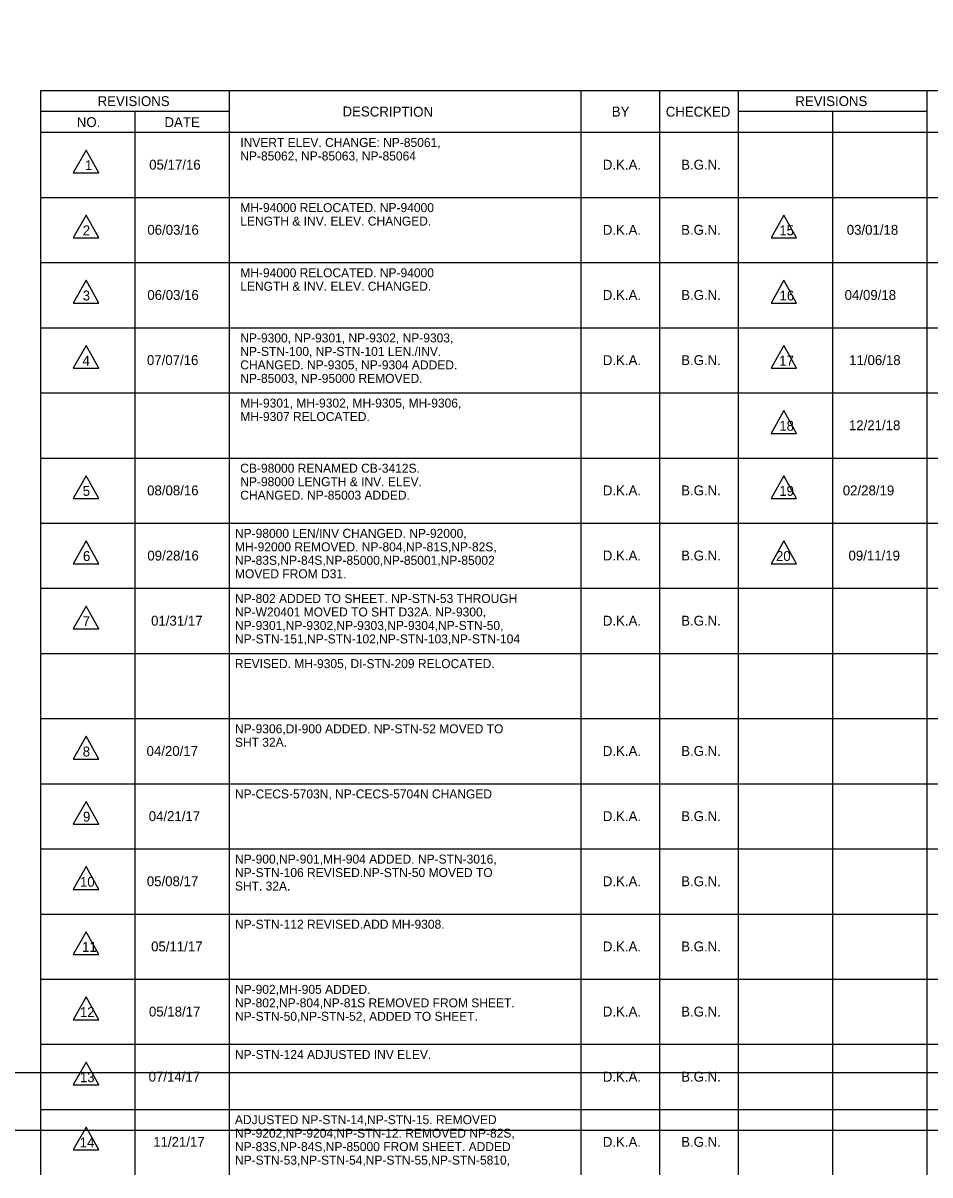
# Model space of a CAD drawing. Extents: x 260980 to 262786, y 322332 to 323393.
# Drawn here: x 261936 to 262340, y 322332 to 322845 of the extents above; entities that cross this region are included whole.
import ezdxf

# ---------------------------------------------------------------- set-up
doc = ezdxf.new("R2010")
doc.units = 0
for name, color, linetype in [('Level 23', 7, 'Continuous'), ('Level 5', 7, 'Continuous'), ('RD_SHT_TX', 7, 'Continuous')]:
    doc.layers.add(name, color=color, linetype=linetype)

msp = doc.modelspace()

# ---------------------------------------------------------------- linework, layer by layer
at = {"layer": 'Level 23'}
msp.add_lwpolyline([(261111.06, 323336.45), (262761.54, 323336.45), (262761.54, 322351.79), (261111.06, 322351.79)], close=True, dxfattribs=at)
msp.add_lwpolyline([(261111.06, 323336.45), (262761.54, 323336.45), (262761.54, 322351.79), (261111.06, 322351.79)], close=True, dxfattribs=at)
at = {"layer": 'Level 5'}
msp.add_lwpolyline([(261111.06, 323310.45), (262762.33, 323310.45), (262762.33, 322377.34), (261111.06, 322377.34)], close=True, dxfattribs=at)
at = {"layer": 'RD_SHT_TX'}
for p, q in [((261944.02, 322814.63), (262254.62, 322814.63)), ((261944.02, 322331.93), (261944.02, 322814.63)), ((262028.02, 322331.93), (262028.02, 322814.63)), ((262184.62, 322331.93), (262184.62, 322814.63)), ((262219.62, 322331.93), (262219.62, 322814.63)), ((262254.62, 322331.93), (262254.62, 322814.63)), ((262254.62, 322814.63), (262565.22, 322814.63)), ((262338.62, 322331.93), (262338.62, 322814.63)), ((262028.02, 322805.28), (261944.02, 322805.28)), ((261986.02, 322331.93), (261986.02, 322805.28)), ((262338.62, 322805.28), (262254.62, 322805.28)), ((262296.62, 322331.93), (262296.62, 322805.28)), ((262565.22, 322795.93), (261944.02, 322795.93)), ((261964.18, 322788.19), (261958.49, 322778.05)), ((261969.88, 322778.05), (261964.18, 322788.19)), ((261958.49, 322778.05), (261969.88, 322778.05)), ((262565.22, 322766.93), (261944.02, 322766.93)), ((261964.18, 322759.19), (261958.49, 322749.05)), ((261969.88, 322749.05), (261964.18, 322759.19)), ((262274.78, 322759.19), (262269.09, 322749.05)), ((262280.48, 322749.05), (262274.78, 322759.19)), ((261958.49, 322749.05), (261969.88, 322749.05)), ((262269.09, 322749.05), (262280.48, 322749.05)), ((262565.22, 322737.93), (261944.02, 322737.93)), ((261964.18, 322730.19), (261958.49, 322720.05)), ((261969.88, 322720.05), (261964.18, 322730.19)), ((262274.78, 322730.19), (262269.09, 322720.05)), ((262280.48, 322720.05), (262274.78, 322730.19)), ((261958.49, 322720.05), (261969.88, 322720.05)), ((262269.09, 322720.05), (262280.48, 322720.05)), ((262565.22, 322708.93), (261944.02, 322708.93)), ((261964.18, 322701.19), (261958.49, 322691.05)), ((261969.88, 322691.05), (261964.18, 322701.19)), ((262274.78, 322701.19), (262269.09, 322691.05)), ((262280.48, 322691.05), (262274.78, 322701.19)), ((261958.49, 322691.05), (261969.88, 322691.05)), ((262269.09, 322691.05), (262280.48, 322691.05)), ((262565.22, 322679.93), (261944.02, 322679.93)), ((262274.78, 322672.19), (262269.09, 322662.05)), ((262280.48, 322662.05), (262274.78, 322672.19)), ((262269.09, 322662.05), (262280.48, 322662.05)), ((262565.22, 322650.93), (261944.02, 322650.93)), ((261964.19, 322643.19), (261958.49, 322633.05)), ((261969.88, 322633.05), (261964.19, 322643.19)), ((262274.78, 322643.19), (262269.09, 322633.05)), ((262280.48, 322633.05), (262274.78, 322643.19)), ((261958.49, 322633.05), (261969.88, 322633.05)), ((262269.09, 322633.05), (262280.48, 322633.05)), ((262565.22, 322621.93), (261944.02, 322621.93)), ((261964.19, 322614.19), (261958.49, 322604.05)), ((261969.88, 322604.05), (261964.19, 322614.19)), ((262274.78, 322614.19), (262269.09, 322604.05)), ((262280.48, 322604.05), (262274.78, 322614.19)), ((261958.49, 322604.05), (261969.88, 322604.05)), ((262269.09, 322604.05), (262280.48, 322604.05)), ((262565.22, 322592.93), (261944.02, 322592.93)), ((261964.19, 322585.19), (261958.49, 322575.05)), ((261969.88, 322575.05), (261964.19, 322585.19)), ((261958.49, 322575.05), (261969.88, 322575.05)), ((262565.22, 322563.93), (261944.02, 322563.93)), ((262565.22, 322534.93), (261944.02, 322534.93)), ((261964.19, 322527.19), (261958.49, 322517.05)), ((261969.88, 322517.05), (261964.19, 322527.19)), ((261958.49, 322517.05), (261969.88, 322517.05)), ((262565.22, 322505.93), (261944.02, 322505.93)), ((261964.19, 322498.19), (261958.49, 322488.05)), ((261969.88, 322488.05), (261964.19, 322498.19)), ((261958.49, 322488.05), (261969.88, 322488.05)), ((262565.22, 322476.93), (261944.02, 322476.93)), ((261964.19, 322469.19), (261958.49, 322459.05)), ((261969.88, 322459.05), (261964.19, 322469.19)), ((261958.49, 322459.05), (261969.88, 322459.05)), ((262565.22, 322447.93), (261944.02, 322447.93)), ((261964.19, 322440.19), (261958.49, 322430.05)), ((261969.88, 322430.05), (261964.19, 322440.19)), ((261958.49, 322430.05), (261969.88, 322430.05)), ((262565.22, 322418.93), (261944.02, 322418.93)), ((261964.19, 322411.19), (261958.49, 322401.05)), ((261969.88, 322401.05), (261964.19, 322411.19)), ((261958.49, 322401.05), (261969.88, 322401.05)), ((262565.22, 322389.93), (261944.02, 322389.93)), ((261964.19, 322382.19), (261958.49, 322372.05)), ((261969.88, 322372.05), (261964.19, 322382.19)), ((261958.49, 322372.05), (261969.88, 322372.05)), ((262565.22, 322360.93), (261944.02, 322360.93)), ((261964.19, 322353.19), (261958.49, 322343.05)), ((261969.88, 322343.05), (261964.19, 322353.19)), ((261958.49, 322343.05), (261969.88, 322343.05))]:
    msp.add_line(p, q, dxfattribs=at)

# ---------------------------------------------------------------- texts
for s, p in [('REVISIONS', (261969.31, 322807.75)), ('REVISIONS', (262279.91, 322807.75)), ('CHECKED', (262222.22, 322803.05)), ('NO.', (261960.04, 322798.4)), ('1', (261963.65, 322779.23)), ('2', (261962.68, 322750.23)), ('15', (262272.73, 322750.23)), ('3', (261962.68, 322721.23)), ('16', (262272.84, 322721.23)), ('4', (261962.57, 322692.23)), ('17', (262272.7, 322692.23)), ('18', (262272.73, 322663.23)), ('5', (261962.68, 322634.23)), ('19', (262272.73, 322634.23)), ('6', (261962.79, 322605.23)), ('20', (262271.28, 322605.23)), ('7', (261962.64, 322576.23)), ('8', (261962.68, 322518.23)), ('9', (261962.79, 322489.23)), ('10', (261961.44, 322460.23)), ('11', (261962.38, 322431.23)), ('12', (261961.4, 322402.23)), ('13', (261961.4, 322373.23)), ('14', (261961.3, 322344.23))]:
    msp.add_text(s, height=4.4, dxfattribs=at).set_placement(p)
for s, height, rotation, p in [('DESCRIPTION', 4.4083, 359.7246, (262078.32, 322803.17)), ('BY', 4.408, 359.7246, (262198.18, 322803.09)), ('DATE', 4.408, 359.7246, (261999.05, 322798.43)), ('INVERT ELEV. CHANGE: NP-85061,', 4, 360, (262032.81, 322789.54)), ('05/17/16', 4.4, 360, (261992.27, 322779.46)), ('NP-85062, NP-85063, NP-85064', 4, 360, (262032.81, 322783.54)), ('D.K.A.', 4.4, 360, (262194.21, 322779.46)), ('B.G.N.', 4.4, 360, (262229.09, 322779.46)), ('MH-94000 RELOCATED. NP-94000 ', 4, 360, (262032.81, 322760.54)), ('LENGTH & INV. ELEV. CHANGED.', 4, 360, (262032.81, 322754.54)), ('06/03/16', 4.4, 360, (261991.45, 322750.46)), ('D.K.A.', 4.4, 360, (262194.21, 322750.46)), ('B.G.N.', 4.4, 360, (262229.08, 322750.46)), ('03/01/18', 4.4, 360, (262302.79, 322750.46)), ('MH-94000 RELOCATED. NP-94000 ', 4, 360, (262032.81, 322731.54)), ('LENGTH & INV. ELEV. CHANGED.', 4, 360, (262032.81, 322725.54)), ('06/03/16', 4.4, 360, (261991.45, 322721.46)), ('D.K.A.', 4.4, 360, (262194.21, 322721.46)), ('B.G.N.', 4.4, 360, (262229.09, 322721.46)), ('04/09/18', 4.4, 360, (262301.84, 322721.46)), ('NP-9300, NP-9301, NP-9302, NP-9303,', 4, 360, (262032.81, 322702.54)), ('07/07/16', 4.4, 360, (261991.27, 322692.46)), ('NP-STN-100, NP-STN-101 LEN./INV.', 4, 360, (262032.81, 322696.54)), ('D.K.A.', 4.4, 360, (262194.21, 322692.46)), ('B.G.N.', 4.4, 360, (262229.09, 322692.46)), ('11/06/18', 4.4, 360, (262303.86, 322692.46)), ('CHANGED. NP-9305, NP-9304 ADDED.', 4, 360, (262032.81, 322690.54)), ('NP-85003, NP-95000 REMOVED.', 4, 360, (262032.81, 322684.54)), ('MH-9301, MH-9302, MH-9305, MH-9306,', 4, 360, (262032.81, 322673.54)), ('MH-9307 RELOCATED. ', 4, 360, (262032.81, 322667.54)), ('12/21/18', 4.4, 360, (262303.75, 322663.46)), ('CB-98000 RENAMED CB-3412S.', 4, 360, (262032.81, 322644.54)), ('NP-98000 LENGTH & INV. ELEV.', 4, 360, (262032.81, 322638.54)), ('08/08/16', 4.4, 360, (261991.35, 322634.46)), ('CHANGED. NP-85003 ADDED.', 4, 360, (262032.81, 322632.54)), ('D.K.A.', 4.4, 360, (262194.21, 322634.46)), ('B.G.N.', 4.4, 360, (262229.09, 322634.46)), ('02/28/19', 4.4, 360, (262301.02, 322634.46)), ('NP-98000 LEN/INV CHANGED. NP-92000, ', 4, 360, (262030.43, 322615.54)), ('09/28/16', 4.4, 360, (261991.45, 322605.46)), ('MH-92000 REMOVED. NP-804,NP-81S,NP-82S,', 4, 360, (262030.43, 322609.54)), ('D.K.A.', 4.4, 360, (262194.21, 322605.46)), ('B.G.N.', 4.4, 360, (262229.09, 322605.46)), ('09/11/19', 4.4, 360, (262303.57, 322605.46)), ('NP-83S,NP-84S,NP-85000,NP-85001,NP-85002', 4, 360, (262030.43, 322603.54)), ('MOVED FROM D31.', 4, 360, (262030.43, 322597.54)), ('NP-802 ADDED TO SHEET. NP-STN-53 THROUGH ', 4, 360, (262030.43, 322586.54)), ('NP-W20401 MOVED TO SHT D32A. NP-9300,', 4, 360, (262030.43, 322580.54)), ('01/31/17', 4.4, 360, (261993.12, 322576.46)), ('D.K.A.', 4.4, 360, (262194.21, 322576.46)), ('B.G.N.', 4.4, 360, (262229.09, 322576.46)), ('NP-9301,NP-9302,NP-9303,NP-9304,NP-STN-50,', 4, 360, (262030.43, 322574.54)), ('NP-STN-151,NP-STN-102,NP-STN-103,NP-STN-104', 4, 360, (262030.43, 322568.54)), ('REVISED. MH-9305, DI-STN-209 RELOCATED.', 4, 360, (262030.43, 322557.54)), ('NP-9306,DI-900 ADDED. NP-STN-52 MOVED TO', 4, 360, (262030.43, 322528.54)), ('04/20/17', 4.4, 360, (261991.1, 322518.46)), ('SHT 32A.', 4, 360, (262030.43, 322522.54)), ('D.K.A.', 4.4, 360, (262194.21, 322518.46)), ('B.G.N.', 4.4, 360, (262229.09, 322518.46)), ('NP-CECS-5703N, NP-CECS-5704N CHANGED', 4, 360, (262030.43, 322499.54)), ('04/21/17', 4.4, 360, (261992.05, 322489.46)), ('D.K.A.', 4.4, 360, (262194.21, 322489.46)), ('B.G.N.', 4.4, 360, (262229.09, 322489.46)), ('NP-900,NP-901,MH-904 ADDED. NP-STN-3016,', 4, 360, (262030.43, 322470.54)), ('NP-STN-106 REVISED.NP-STN-50 MOVED TO', 4, 360, (262030.43, 322464.54)), ('05/08/17', 4.4, 360, (261991.2, 322460.46)), ('SHT. 32A.', 4, 360, (262030.43, 322458.54)), ('D.K.A.', 4.4, 360, (262194.21, 322460.46)), ('B.G.N.', 4.4, 360, (262229.09, 322460.46)), ('NP-STN-112 REVISED.ADD MH-9308.', 4, 360, (262030.43, 322441.54)), ('05/11/17', 4.4, 360, (261993.12, 322431.46)), ('D.K.A.', 4.4, 360, (262194.21, 322431.46)), ('B.G.N.', 4.4, 360, (262229.09, 322431.46)), ('NP-902,MH-905 ADDED.', 4, 360, (262030.43, 322412.54)), ('NP-802,NP-804,NP-81S REMOVED FROM SHEET.', 4, 360, (262030.43, 322406.54)), ('05/18/17', 4.4, 360, (261992.16, 322402.46)), ('NP-STN-50,NP-STN-52, ADDED TO SHEET.', 4, 360, (262030.43, 322400.54)), ('D.K.A.', 4.4, 360, (262194.21, 322402.46)), ('B.G.N.', 4.4, 360, (262229.09, 322402.46)), ('NP-STN-124 ADJUSTED INV ELEV.', 4, 360, (262030.43, 322383.54)), ('07/14/17', 4.4, 360, (261992.02, 322373.46)), ('D.K.A.', 4.4, 360, (262194.21, 322373.46)), ('B.G.N.', 4.4, 360, (262229.09, 322373.46)), ('ADJUSTED NP-STN-14,NP-STN-15. REMOVED ', 4, 360, (262030.43, 322354.54)), ('11/21/17', 4.4, 360, (261994.07, 322344.46)), ('NP-9202,NP-9204,NP-STN-12. REMOVED NP-82S,', 4, 360, (262030.43, 322348.54)), ('D.K.A.', 4.4, 360, (262194.21, 322344.46)), ('B.G.N.', 4.4, 360, (262229.09, 322344.46)), ('NP-83S,NP-84S,NP-85000 FROM SHEET. ADDED', 4, 360, (262030.43, 322342.54)), ('NP-STN-53,NP-STN-54,NP-STN-55,NP-STN-5810,', 4, 360, (262030.43, 322336.54))]:
    msp.add_text(s, height=height, rotation=rotation, dxfattribs=at).set_placement(p)

doc.saveas('drawing.dxf')
